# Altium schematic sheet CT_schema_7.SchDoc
size 278 x 170 mm
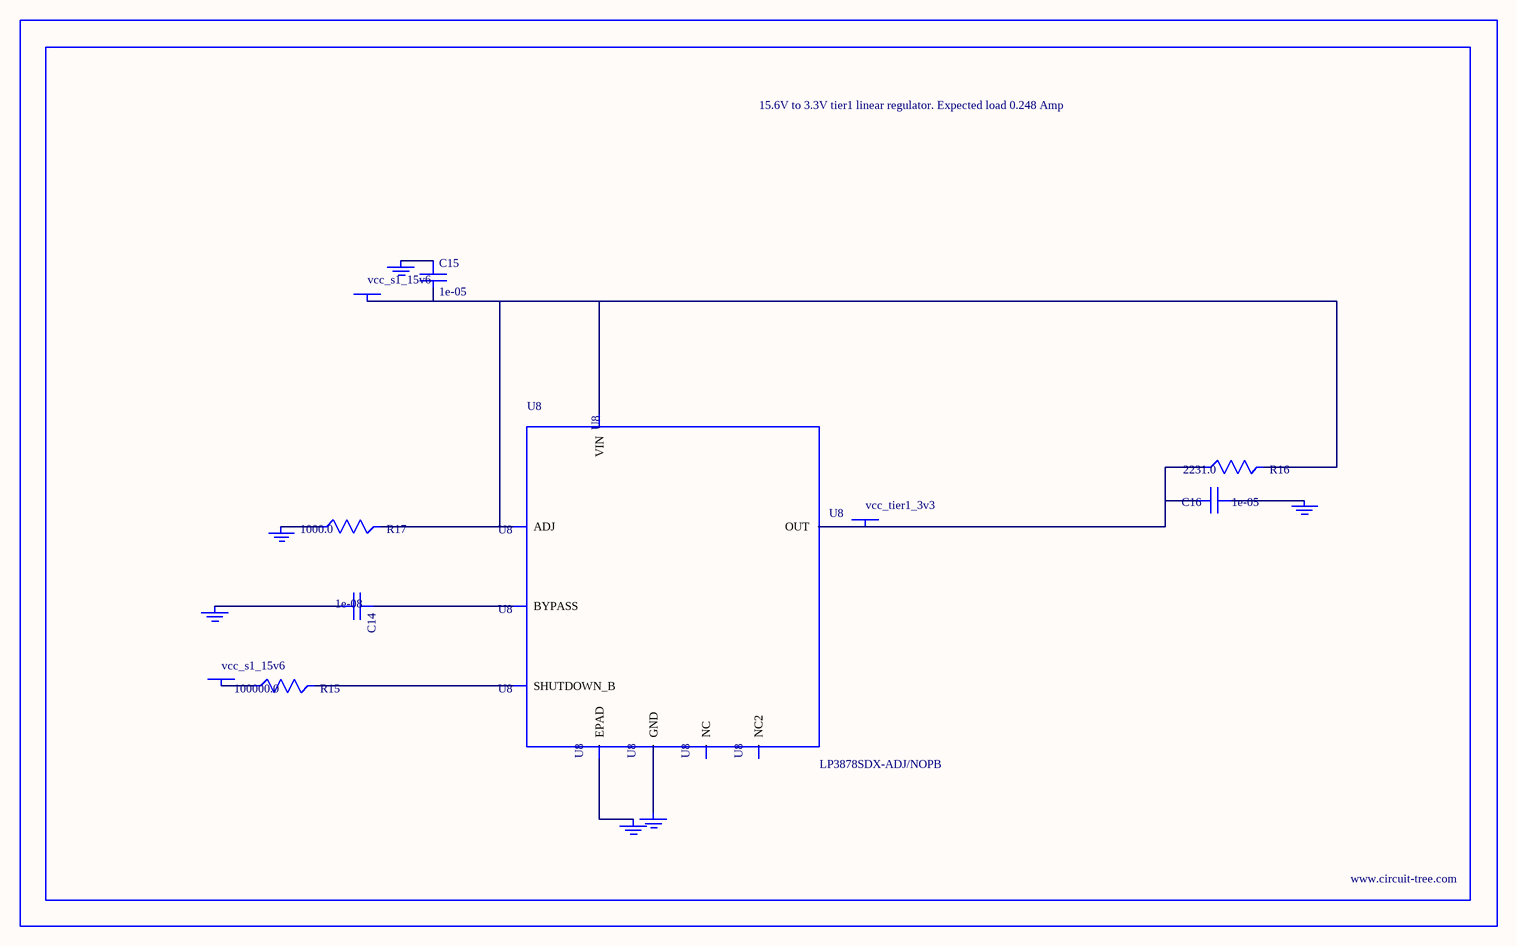
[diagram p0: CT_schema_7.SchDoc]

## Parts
BORDER6  (no value)
C14  1e-08  [C0402]
C15  1e-05  [C1210]
C16  1e-05  [C1210]
GND_INSTANCE_6_0  (no value)
GND_INSTANCE_6_1  (no value)
GND_INSTANCE_6_2  (no value)
GND_INSTANCE_6_3  (no value)
GND_INSTANCE_6_4  (no value)
GND_INSTANCE_6_5  (no value)
POWER_INSTANCE_6_0  vcc_s1_15v6
POWER_INSTANCE_6_1  vcc_s1_15v6
POWER_INSTANCE_6_2  vcc_tier1_3v3
R15  100000.0  [R0603]
R16  2231.0  [R0603]
R17  1000.0  [R0603]
U8  LP3878SDX-ADJ/NOPB  [WSON-8]

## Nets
NetC14_1: C14.1 U8.1(BYPASS)
NetC14_2: C14.2 GND_INSTANCE_6_0.0(GND)
NetC15_1: C15.1 GND_INSTANCE_6_1.0(GND)
NetC15_2: C15.2 POWER_INSTANCE_6_0.0(PWR) R16.2 R17.2 U8.4(VIN) U8.6(ADJ)
NetC16_1: C16.1 GND_INSTANCE_6_2.0(GND)
NetC16_2: C16.2 POWER_INSTANCE_6_2.0(PWR) R16.1 U8.5(OUT)
NetGND_INSTANCE_6_3_0: GND_INSTANCE_6_3.0(GND) R17.1
NetGND_INSTANCE_6_4_0: GND_INSTANCE_6_4.0(GND) U8.PAD(EPAD)
NetGND_INSTANCE_6_5_0: GND_INSTANCE_6_5.0(GND) U8.3(GND)
NetPOWER_INSTANCE_6_1_0: POWER_INSTANCE_6_1.0(PWR) R15.1
NetR15_2: R15.2 U8.8(SHUTDOWN_B)

Not connected (* = marked no-connect by the designer): U8 2(NC) 7(NC2)

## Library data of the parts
BORDER6 = BORDER_PAGE6
C14 = C0402C103K3RAC
C15 = C1210C106K5PACTU
C16 = GRM32DR61E106MA12L
GND_INSTANCE_6_0-GND_INSTANCE_6_5 = GND
POWER_INSTANCE_6_0-POWER_INSTANCE_6_2 = PWR
R15 = RC0603JR-07100KL
R16 = R16
R17 = RC0603JR-071KL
